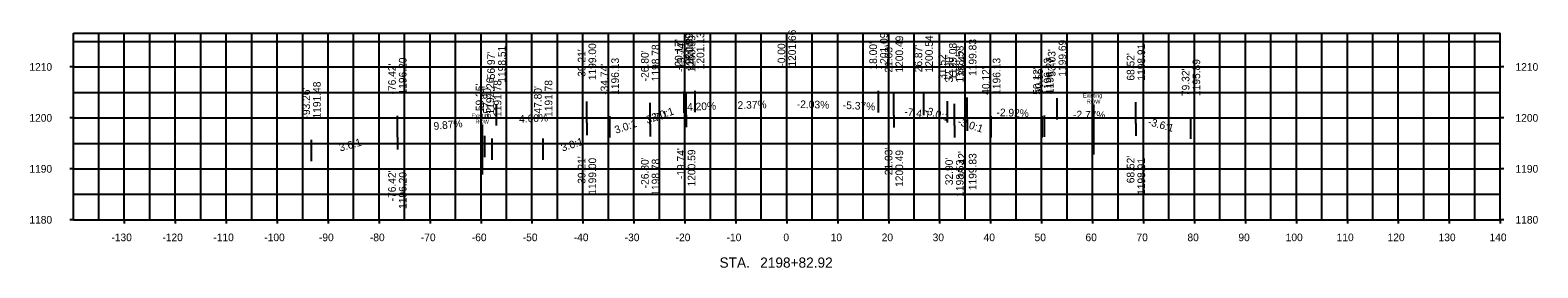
# Model space of a CAD drawing. Extents: x -148 to 147, y 1171 to 1217.
import ezdxf

# ---------------------------------------------------------------- set-up
doc = ezdxf.new("R2010")
doc.units = 0
for name, color, linetype in [('Default', 7, 'Continuous'), ('ROW', 7, 'Continuous'), ('SheetBorder', 7, 'Continuous'), ('SheetGridMajor', 7, 'Continuous'), ('SheetGridMinor', 7, 'Continuous'), ('Text', 7, 'Continuous')]:
    doc.layers.add(name, color=color, linetype=linetype)

msp = doc.modelspace()

# ---------------------------------------------------------------- linework, layer by layer
at = {"layer": 'ROW'}
for p, q in [((60.2, 1202.64), (60.2, 1192.8)), ((-59.78, 1198.71), (-59.78, 1188.87))]:
    msp.add_line(p, q, dxfattribs=at)
at = {"layer": 'SheetBorder'}
for p, q in [((-140, 1216.66), (140, 1216.66)), ((-140, 1180), (-140, 1216.66)), ((140, 1180), (140, 1216.66)), ((-140, 1180), (140, 1180))]:
    msp.add_line(p, q, dxfattribs=at)
at = {"layer": 'SheetGridMajor'}
for p, q in [((-130, 1180), (-130, 1216.66)), ((-120, 1180), (-120, 1216.66)), ((-110, 1180), (-110, 1216.66)), ((-100, 1180), (-100, 1216.66)), ((-90, 1180), (-90, 1216.66)), ((-80, 1180), (-80, 1216.66)), ((-70, 1180), (-70, 1216.66)), ((-60, 1180), (-60, 1216.66)), ((-50, 1180), (-50, 1216.66)), ((-40, 1180), (-40, 1216.66)), ((-30, 1180), (-30, 1216.66)), ((-20, 1180), (-20, 1216.66)), ((-10, 1180), (-10, 1216.66)), ((0, 1180), (0, 1216.66)), ((10, 1180), (10, 1216.66)), ((20, 1180), (20, 1216.66)), ((30, 1180), (30, 1216.66)), ((40, 1180), (40, 1216.66)), ((50, 1180), (50, 1216.66)), ((60, 1180), (60, 1216.66)), ((70, 1180), (70, 1216.66)), ((80, 1180), (80, 1216.66)), ((90, 1180), (90, 1216.66)), ((100, 1180), (100, 1216.66)), ((110, 1180), (110, 1216.66)), ((120, 1180), (120, 1216.66)), ((130, 1180), (130, 1216.66)), ((140, 1180), (140, 1216.66)), ((-140, 1210), (-140.72, 1210)), ((-140, 1210), (140, 1210)), ((140.72, 1210), (140, 1210)), ((-140, 1200), (-140.72, 1200)), ((-140, 1200), (140, 1200)), ((140.72, 1200), (140, 1200)), ((-140, 1190), (-140.72, 1190)), ((-140, 1190), (140, 1190)), ((140.72, 1190), (140, 1190)), ((-140, 1180), (-140.72, 1180)), ((-130, 1180), (-130, 1179.28)), ((-120, 1180), (-120, 1179.28)), ((-110, 1180), (-110, 1179.28)), ((-100, 1180), (-100, 1179.28)), ((-90, 1180), (-90, 1179.28)), ((-80, 1180), (-80, 1179.28)), ((-70, 1180), (-70, 1179.28)), ((-60, 1180), (-60, 1179.28)), ((-50, 1180), (-50, 1179.28)), ((-40, 1180), (-40, 1179.28)), ((-30, 1180), (-30, 1179.28)), ((-20, 1180), (-20, 1179.28)), ((-10, 1180), (-10, 1179.28)), ((0, 1180), (0, 1179.28)), ((10, 1180), (10, 1179.28)), ((20, 1180), (20, 1179.28)), ((30, 1180), (30, 1179.28)), ((40, 1180), (40, 1179.28)), ((50, 1180), (50, 1179.28)), ((60, 1180), (60, 1179.28)), ((70, 1180), (70, 1179.28)), ((80, 1180), (80, 1179.28)), ((90, 1180), (90, 1179.28)), ((100, 1180), (100, 1179.28)), ((110, 1180), (110, 1179.28)), ((120, 1180), (120, 1179.28)), ((130, 1180), (130, 1179.28)), ((140, 1180), (140, 1179.28)), ((140.72, 1180), (140, 1180))]:
    msp.add_line(p, q, dxfattribs=at)
at = {"layer": 'SheetGridMinor'}
for p, q in [((-135, 1180), (-135, 1216.66)), ((-125, 1180), (-125, 1216.66)), ((-115, 1180), (-115, 1216.66)), ((-105, 1180), (-105, 1216.66)), ((-95, 1180), (-95, 1216.66)), ((-85, 1180), (-85, 1216.66)), ((-75, 1180), (-75, 1216.66)), ((-65, 1180), (-65, 1216.66)), ((-55, 1180), (-55, 1216.66)), ((-45, 1180), (-45, 1216.66)), ((-35, 1180), (-35, 1216.66)), ((-25, 1180), (-25, 1216.66)), ((-15, 1180), (-15, 1216.66)), ((-5, 1180), (-5, 1216.66)), ((5, 1180), (5, 1216.66)), ((15, 1180), (15, 1216.66)), ((25, 1180), (25, 1216.66)), ((35, 1180), (35, 1216.66)), ((45, 1180), (45, 1216.66)), ((55, 1180), (55, 1216.66)), ((65, 1180), (65, 1216.66)), ((75, 1180), (75, 1216.66)), ((85, 1180), (85, 1216.66)), ((95, 1180), (95, 1216.66)), ((105, 1180), (105, 1216.66)), ((115, 1180), (115, 1216.66)), ((125, 1180), (125, 1216.66)), ((135, 1180), (135, 1216.66)), ((-140, 1215), (140, 1215)), ((-140, 1205), (140, 1205)), ((-140, 1195), (140, 1195)), ((-140, 1185), (140, 1185))]:
    msp.add_line(p, q, dxfattribs=at)
at = {"layer": 'Text'}
for p, q in [((-20.17, 1200.99), (-20.17, 1205.19)), ((-19.74, 1200.59), (-19.74, 1204.79)), ((-19.74, 1200.59), (-19.74, 1204.79)), ((-18, 1201.13), (-18, 1205.33)), ((0, 1201.66), (0, 1205.86)), ((18, 1201.09), (18, 1205.29)), ((21.03, 1200.49), (21.03, 1204.69)), ((26.87, 1200.54), (26.87, 1204.74)), ((-56.97, 1198.51), (-56.97, 1202.71)), ((-39.21, 1199), (-39.21, 1203.2)), ((-39.21, 1199), (-39.21, 1203.2)), ((-26.8, 1198.78), (-26.8, 1202.98)), ((31.52, 1199.08), (31.52, 1203.28)), ((32.9, 1198.53), (32.9, 1202.73)), ((32.9, 1198.53), (32.9, 1202.73)), ((35.42, 1199.83), (35.42, 1204.03)), ((53.03, 1199.69), (53.03, 1203.89)), ((68.52, 1198.91), (68.52, 1203.11)), ((68.52, 1198.91), (68.52, 1203.11)), ((-76.42, 1196.2), (-76.42, 1200.4)), ((-39.21, 1199), (-39.21, 1196.6)), ((-34.74, 1196.13), (-34.74, 1200.33)), ((-26.8, 1198.78), (-26.8, 1196.38)), ((-19.74, 1200.59), (-19.74, 1198.19)), ((21.03, 1200.49), (21.03, 1198.09)), ((32.9, 1198.53), (32.9, 1196.13)), ((35.42, 1199.83), (35.42, 1197.43)), ((40.12, 1196.13), (40.12, 1200.33)), ((40.12, 1196.13), (40.12, 1200.33)), ((50.12, 1196.13), (50.12, 1200.33)), ((50.55, 1196.27), (50.55, 1200.47)), ((68.52, 1198.91), (68.52, 1196.51)), ((79.32, 1195.89), (79.32, 1200.09)), ((-93.26, 1191.48), (-93.26, 1195.68)), ((-76.42, 1196.2), (-76.42, 1193.8)), ((-59.25, 1192.26), (-59.25, 1196.46)), ((-57.8, 1191.78), (-57.8, 1195.98)), ((-47.8, 1191.78), (-47.8, 1195.98))]:
    msp.add_line(p, q, dxfattribs=at)

# ---------------------------------------------------------------- texts
at = {"layer": 'Default'}
for s, height, p in [('1210', 1.5, (-148.63, 1209.25)), ('1210', 1.5, (143, 1209.25)), ('1200', 1.5, (-148.63, 1199.25)), ('1200', 1.5, (143, 1199.25)), ('1190', 1.5, (-148.63, 1189.25)), ('1190', 1.5, (143, 1189.25)), ('1180', 1.5, (-148.63, 1179.25)), ('1180', 1.5, (143, 1179.25)), ('-130', 1.5, (-132.53, 1175.8)), ('-120', 1.5, (-122.53, 1175.8)), ('-110', 1.5, (-112.53, 1175.8)), ('-100', 1.5, (-102.53, 1175.8)), ('-90', 1.5, (-91.81, 1175.8)), ('-80', 1.5, (-81.81, 1175.8)), ('-70', 1.5, (-71.81, 1175.8)), ('-60', 1.5, (-61.81, 1175.8)), ('-50', 1.5, (-51.81, 1175.8)), ('-40', 1.5, (-41.81, 1175.8)), ('-30', 1.5, (-31.81, 1175.8)), ('-20', 1.5, (-21.81, 1175.8)), ('-10', 1.5, (-11.81, 1175.8)), ('0', 1.5, (-0.67, 1175.8)), ('10', 1.5, (8.62, 1175.8)), ('20', 1.5, (18.62, 1175.8)), ('30', 1.5, (28.62, 1175.8)), ('40', 1.5, (38.62, 1175.8)), ('50', 1.5, (48.62, 1175.8)), ('60', 1.5, (58.62, 1175.8)), ('70', 1.5, (68.62, 1175.8)), ('80', 1.5, (78.62, 1175.8)), ('90', 1.5, (88.62, 1175.8)), ('100', 1.5, (97.9, 1175.8)), ('110', 1.5, (107.9, 1175.8)), ('120', 1.5, (117.9, 1175.8)), ('130', 1.5, (127.9, 1175.8)), ('140', 1.5, (137.9, 1175.8)), ('STA.', 2.004, (-13.2, 1170.6)), ('2198+82.92', 2.004, (-5.22, 1170.6))]:
    msp.add_text(s, height=height, dxfattribs=at).set_placement(p)
at = {"layer": 'ROW'}
for s, p in [('Existing', (58.11, 1203.99)), ('ROW', (58.88, 1202.81)), ('Existing', (-61.87, 1200.07)), ('ROW', (-61.1, 1198.88))]:
    msp.add_text(s, height=0.787, dxfattribs=at).set_placement(p)
at = {"layer": 'Text'}
for s, rotation, p in [('1200.99', 90, (-18.37, 1209.39)), ('1200.59', 90, (-17.94, 1208.99)), ('1200.59', 90, (-17.94, 1208.99)), ('1201.13', 90, (-16.2, 1209.53)), ('1201.66', 90, (1.8, 1210.06)), ('1201.09', 90, (19.8, 1209.49)), ('1200.49', 90, (22.83, 1208.89)), ('1200.54', 90, (28.67, 1208.94)), ('1198.51', 90, (-55.17, 1206.91)), ("-39.21'", 90, (-39.51, 1207.4)), ("-39.21'", 90, (-39.51, 1207.4)), ('1199.00', 90, (-37.41, 1207.4)), ('1199.00', 90, (-37.41, 1207.4)), ("-26.80'", 90, (-27.1, 1207.18)), ('1198.78', 90, (-25, 1207.18)), ("-20.17'", 90, (-20.47, 1209.39)), ("-19.74'", 90, (-20.04, 1208.99)), ("-19.74'", 90, (-20.04, 1208.99)), ("-18.00'", 90, (-18.3, 1209.53)), ("-0.00'", 90, (-0.3, 1210.06)), ("18.00'", 90, (17.7, 1209.49)), ("21.03'", 90, (20.73, 1208.89)), ("26.87'", 90, (26.57, 1208.94)), ('1199.08', 90, (33.32, 1207.48)), ('1198.53', 90, (34.7, 1206.93)), ('1198.53', 90, (34.7, 1206.93)), ("35.42'", 90, (35.12, 1208.23)), ('1199.83', 90, (37.22, 1208.23)), ("53.03'", 90, (52.73, 1208.09)), ('1199.69', 90, (54.83, 1208.09)), ('1198.91', 90, (70.32, 1207.31)), ('1198.91', 90, (70.32, 1207.31)), ("-76.42'", 90, (-76.72, 1204.6)), ('1196.20', 90, (-74.62, 1204.6)), ("-56.97'", 90, (-57.27, 1206.91)), ("-34.74'", 90, (-35.04, 1204.53)), ('1196.13', 90, (-32.94, 1204.53)), ("31.52'", 90, (31.22, 1207.48)), ("32.90'", 90, (32.6, 1206.93)), ("32.90'", 90, (32.6, 1206.93)), ('1196.13', 90, (41.92, 1204.53)), ('1196.13', 90, (41.92, 1204.53)), ('1196.13', 90, (51.92, 1204.53)), ('1196.27', 90, (52.35, 1204.67)), ("68.52'", 90, (68.22, 1207.31)), ("68.52'", 90, (68.22, 1207.31)), ('1195.89', 90, (81.12, 1204.29)), ('1192.26', 90, (-57.45, 1200.66)), ('1191.78', 90, (-56, 1200.18)), ('1191.78', 90, (-46, 1200.18)), ("40.12'", 90, (39.82, 1204.53)), ("40.12'", 90, (39.82, 1204.53)), ("50.12'", 90, (49.82, 1204.53)), ("50.55'", 90, (50.25, 1204.67)), ("79.32'", 90, (79.02, 1204.29)), ("-93.26'", 90, (-93.56, 1199.88)), ('1191.48', 90, (-91.46, 1199.88)), ("-59.25'", 90, (-59.55, 1200.66)), ("-57.80'", 90, (-58.1, 1200.18)), ("-47.80'", 90, (-48.1, 1200.18)), ('3.7:1', 15.0466, (-27.42, 1198.85)), ('3.0:1', 18.4332, (-26.23, 1199.3)), ('4.20%', 2.4043, (-19.54, 1201.39)), ('2.37%', 1.3587, (-9.64, 1201.76)), ('-2.03%', 358.8381, (1.96, 1201.95)), ('-5.37%', 356.9288, (10.97, 1201.79)), ('-7.4:1', 352.3386, (23, 1200.53)), ('-3.0:1', 341.5668, (26.76, 1200.91)), ('-2.92%', 358.3257, (41.13, 1200.36)), ('-2.77%', 358.4124, (56.15, 1199.93)), ('9.87%', 5.6341, (-69.24, 1197.63)), ('4.60%', 2.6333, (-52.5, 1199.05)), ('3.0:1', 18.4332, (-33.51, 1196.87)), ('-3.0:1', 341.5668, (33.38, 1198.71)), ('-3.6:1', 344.3607, (70.75, 1198.62)), ('3.6:1', 15.6597, (-87.62, 1193.39)), ('3.0:1', 18.4332, (-44.01, 1193.37)), ("-39.21'", 90, (-39.51, 1186.4)), ("-19.74'", 90, (-20.04, 1187.99)), ('1200.59', 90, (-17.94, 1186.55)), ("21.03'", 90, (20.73, 1188.75)), ('1200.49', 90, (22.83, 1186.45)), ("35.42'", 90, (35.12, 1188.08)), ('1199.83', 90, (37.22, 1185.81)), ("68.52'", 90, (68.22, 1187.17)), ("-76.42'", 90, (-76.72, 1183.61)), ('1199.00', 90, (-37.41, 1184.92)), ("-26.80'", 90, (-27.1, 1186.18)), ('1198.78', 90, (-25, 1184.73)), ("32.90'", 90, (32.6, 1186.79)), ('1198.53', 90, (34.7, 1184.52)), ('1198.91', 90, (70.32, 1184.88)), ('1196.20', 90, (-74.62, 1182.13))]:
    msp.add_text(s, height=1.5, rotation=rotation, dxfattribs=at).set_placement(p)

doc.saveas('drawing.dxf')
